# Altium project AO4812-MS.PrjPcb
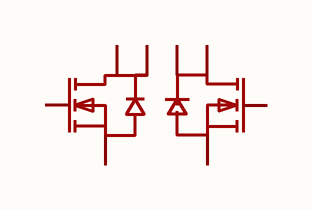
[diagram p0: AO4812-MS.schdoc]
1 sheet, 1 parts. Net scope: global (net labels, ports and power ports of the same name join across sheets).

## Sheet AO4812-MS.schdoc
size 127 x 101 mm

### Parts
Q?  ao4812-ms  [SOP-8_L4.9-W3.9-P1.27-LS6.0-BL]  (value not drawn)

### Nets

Not connected (* = marked no-connect by the designer): Q? 1(S1) 2(G1) 3(S2) 4(G2) 5(D2) 6(D2) 7(D1) 8(D1)

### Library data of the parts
Q? = ao4812-ms: 数量:2个N沟道;漏源电压(Vdss):30V;连续漏极电流(Id):9A;导通电阻(RDS(on)):30mΩ@10V;耗散功率(Pd):2W;阈值电压(Vgs(th)):2.4V@250uA;; Manufacturer: MSKSEMI(美森科); AddInBom: yes; ModelId: 75c24a7891ee4dd6bdac16a7163ff87e; ModelName: SOP-8_L4.9-W3.9-P1.27-LS6.0-BL-1; ModelTransform: 192.913,236.22,0,0,0,0,-0.393,2.749,0; Number: 2个N沟道; Drain to Source Voltage: 30V; Current - Continuous Drain(Id): 9A; Pd - Power Dissipation: 2W; Gate Charge(Qg): 6.3nC@10V; Input Capacitance(Ciss): 310pF; Reverse Transfer Capacitance (Crss@Vds): 50pF; Type: N沟道; Output Capacitance(Coss): 45pF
